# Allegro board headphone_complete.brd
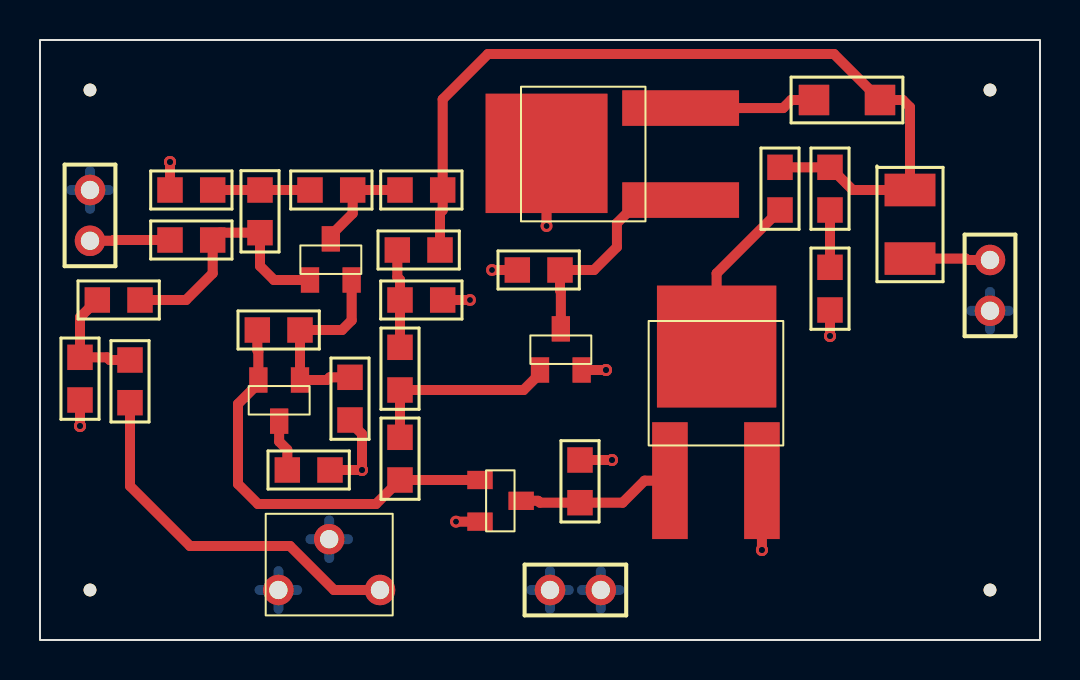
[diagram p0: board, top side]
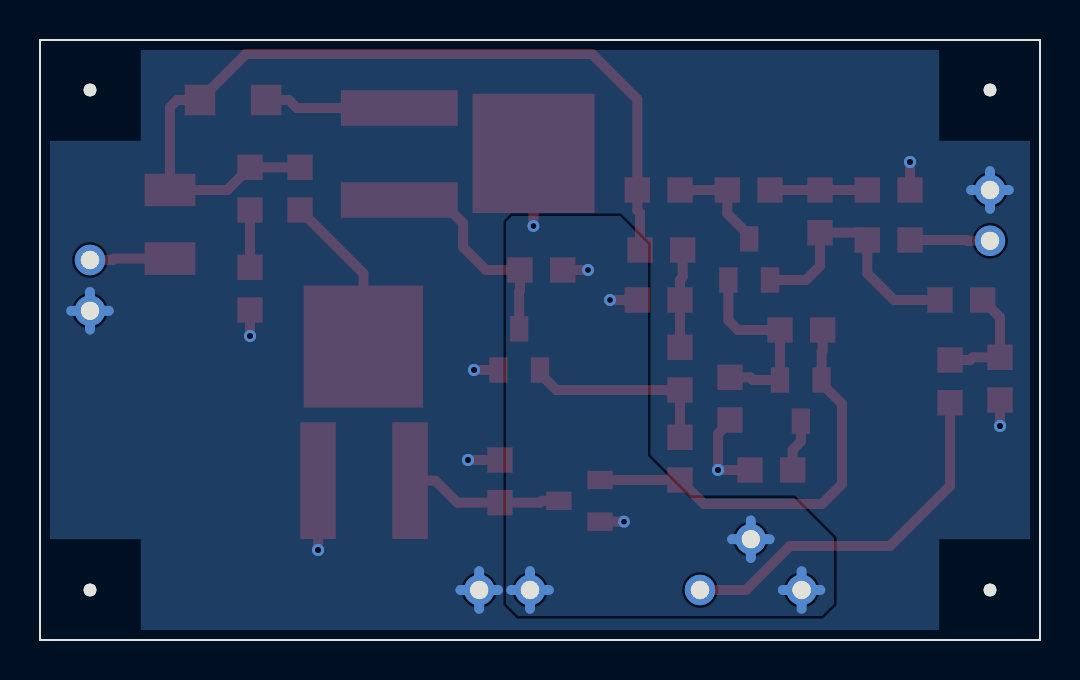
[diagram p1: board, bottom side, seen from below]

Outline 50 x 30 mm; copper layers: TOP, BOTTOM. Coordinates in mm from the lower left corner of the outline.
Outline path: rectangle 0,0 50,30

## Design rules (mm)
constraint set DEFAULT: min track width 0.5

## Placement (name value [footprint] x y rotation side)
C1  47u  [SMC0805]  20 19.5 180 top
C2  47u  [SMC0805]  2 12 90 top
C3  47u  [SMC0805]  13.5 22.5 0 top
C4  2200u  [SMC1210]  43.5 22.5 270 top
C5  0.47u  [SMC0805]  6.5 20 0 top
C6  10p  [SMC0805]  13 15.5 180 top
C7  0.1u  [SMC0805]  39.5 16.5 90 top
J1  HEADER 2  [JUMPER2]  2.5 22.5 270 top
J2  HEADER 2  [JUMPER2]  47.5 19 270 top
J3  HEADER 2  [JUMPER2]  25.5 2.5 0 top
NOREF  -  [unnamed]  47.5 27.5 0 top
NOREF#2  -  [unnamed]  47.5 2.5 0 top
NOREF#3  -  [unnamed]  2.5 27.5 0 top
NOREF#4  -  [unnamed]  2.5 2.5 0 top
Q1  TIP41  [TO252AA]  32 22 90 top
Q2  BC212AP/ZTX  [TO236AB]  25 13.5 270 top
Q3  BC212AP/ZTX  [TO236AB]  13.5 18 270 top
Q4  BC182BP/ZTX  [TO236AB]  22 8 180 top
Q5  TIP42  [TO252AA]  31.5 8 0 top
Q6  BC182BP/ZTX  [TO236AB]  13 13 90 top
R1  3k3  [SMR0805]  18 17 0 top
R2  1k8  [SMR0805]  26 18.5 180 top
R3  50k  [RESADJ]  17 2.5 270 top
R4  3k3  [SMR0805]  18 12.5 90 top
R5  22k  [SMR0805]  4.5 14 270 top
R6  2k2  [SMR0805]  18 22.5 0 top
R7  10  [SMR1206]  42 27 180 top
R8  560  [SMR0805]  18 8 90 top
R9  100k  [SMR0805]  5 17 180 top
R10  10  [SMR0805]  37 21.5 90 top
R11  10  [SMR0805]  39.5 21.5 90 top
R12  120k  [SMR0805]  11 22.5 270 top
R13  220  [SMR0805]  6.5 22.5 0 top
R14  2k2  [SMR0805]  15.5 11 90 top
R15  100  [SMR0805]  14.5 8.5 180 top
R16  1k8  [SMR0805]  27 9 270 top

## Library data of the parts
C1-C7 = C
J1-J3 = HEADER 2: User Part Number: ***
Q1 = TIP41
Q2 Q3 = BC212AP/ZTX_0
Q4 Q6 = BC182BP/ZTX_0
Q5 = TIP42
R1 R2 R4-R16 = R
R3 = POT: Tolerance: ***; User Part Number: ***

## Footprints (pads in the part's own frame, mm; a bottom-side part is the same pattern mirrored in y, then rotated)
JUMPER2
  round 1.524 hole 0.914: 1(0,0) 2(2.54,0)
RESADJ
  round 1.524 hole 0.914: 1(0,0) 2(-2.54,-2.54) 3(0,-5.08)
SMC0805
  rect 1.27x1.27 smd: 1(0,0) 2(2.134,0)
SMC1210
  rect 1.626x2.54 smd: 1(0,0) 2(3.429,0)
SMR0805
  rect 1.27x1.27 smd: 1(0,0) 2(2.134,0)
SMR1206
  rect 1.524x1.524 smd: 1(0,0) 2(3.302,0)
TO236AB
  rect 1.27x0.914 smd: 1(0,0) 2(0,2.083) 3(-2.057,1.041)
TO252AA
  rect 1.778x5.842 smd: 1(-0.004,-0.034) 3(4.596,-0.034)
  rect 5.969x6.096 smd: 2(2.332,6.673)
unnamed
  round 0.635 hole 3.175 unplated: (0,0)

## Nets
0: C2.1 C7.1 J1.1 J2.2 J3.2 Q2.2 Q5.3(E) R13.1 R14.1 R15.1 R16.1
IN: C5.1 J1.2
MID: C1.1 C4.1 R6.2 R7.1 R10.2 R11.2
OUT: C4.2 J2.1
VPP: J3.1 Q1.2 Q4.2 R1.2 R2.2 R3.2(T) R3.3
N1519156: C1.2 R1.1 R4.2
N1519228: Q1.1 Q2.3(E) R2.1
N1519232: R3.1 R5.2
N1519306: Q1.3(E) R7.2
N1519352: Q2.1 R4.1 R8.2
N1519356: C2.2 R5.1 R9.2
N1519362: C3.2 Q3.3(E) R6.1
N1519474: C3.1 R12.1 R13.2
N1519554: C6.2 Q4.1 Q6.2 R8.1
N1519560: C5.2 Q3.1 R9.1 R12.2
N1519748: C6.1 Q3.2 Q6.1 R14.2
N1519802: Q5.2 R10.1
N1519808: C7.2 R11.1
N1519834: Q4.3(E) Q5.1 R16.2
N1519922: Q6.3(E) R15.2

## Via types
v1: diameter 0.6, hole 0.3, TOP to BOTTOM, 18 vias

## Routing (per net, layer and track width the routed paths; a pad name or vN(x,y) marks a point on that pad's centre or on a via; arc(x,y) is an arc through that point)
0: length 25.9
  TOP w0.5: v1(39.5,15.2) C7.1 ; R14.1 15.5,10.9 16.1,10.3 v1(16.1,8.5) R15.1 ; v1(28.3,13.5) Q2.2 ; R13.1 v1(6.5,23.9) ; v1(2,10.7) C2.1 ; Q5.3 v1(36.1,4.5) ; R16.1 v1(28.6,9)
  BOTTOM w0.5: J1.1 2.5,23.44 ; J1.1 2.5,21.56 ; J1.1 1.56,22.5 ; J1.1 3.44,22.5 ; J2.2 48.44,16.46 ; J2.2 47.5,15.52 ; J2.2 46.56,16.46 ; J2.2 47.5,17.4 ; 28.04,1.56 J3.2 ; J3.2 28.04,3.44 ; J3.2 28.98,2.5 ; J3.2 27.1,2.5
IN: length 4
  TOP w0.5: J1.2 3.64,19.96 3.68,20 C5.1
MID: length 44.1
  TOP w0.5: C1.1 20,21.35 20.13,21.49 R6.2 20.13,27.03 22.4,29.3 39.7,29.3 R7.1 43.14,27 43.5,26.64 C4.1 40.63,22.5 R11.2 R10.2
OUT: length 4
  TOP w0.5: C4.2 46.29,19.07 46.36,19 J2.1
VPP: length 18.7
  TOP w0.5: R1.2 v1(21.5,17) ; Q1.2 v1(25.33,20.7) ; R2.2 v1(22.6,18.5) ; v1(20.8,5.92) Q4.2
  BOTTOM w0.5: 24.56,2.5 J3.1 ; J3.1 25.5,3.44 ; J3.1 26.44,2.5 ; J3.1 25.5,1.56 ; R3.2 14.46,5.98 ; R3.2 13.52,5.04 ; R3.2 14.46,4.1 ; R3.2 15.4,5.04 ; 11.92,1.56 R3.3 ; R3.3 10.98,2.5 ; R3.3 11.92,3.44 ; R3.3 12.86,2.5
N1519156: length 4.9
  TOP w0.5: R4.2 R1.1 18,18.01 17.87,18.15 C1.2
N1519228: length 11.1
  TOP w0.5: Q2.3 26.04,17.45 26,17.49 R2.1 27.7,18.5 28.85,19.65 28.85,20.84 30,22 Q1.1
N1519232: length 18.8
  TOP w0.5: R5.2 4.5,7.7 7.5,4.7 12.5,4.7 14.7,2.5 R3.1
N1519306: length 6.8
  TOP w0.5: R7.2 37.56,27 37.16,26.6 Q1.3
N1519352: length 9.9
  TOP w0.5: Q2.1 25,13.32 24.18,12.5 R4.1 R8.2
N1519356: length 5.8
  TOP w0.5: R5.1 3.49,14 3.35,14.13 C2.2 2,16.13 R9.2
N1519362: length 5.3
  TOP w0.5: Q3.3 14.54,20.24 15.63,21.33 C3.2 R6.1
N1519474: length 4.9
  TOP w0.5: R13.2 R12.1 C3.1
N1519554: length 21.2
  TOP w0.5: Q4.1 R8.1 16.8,6.8 10.9,6.8 9.9,7.8 9.9,11.8 10.92,12.82 Q6.2 10.92,14.44 10.87,14.49 C6.2
N1519560: length 12.8
  TOP w0.5: R9.1 7.3,17 8.63,18.33 C5.2 9,20.37 R12.2 11,18.7 11.7,18 Q3.1
N1519748: length 9.9
  TOP w0.5: R14.2 14.49,13.13 14.35,13 Q6.1 C6.1 15.1,15.5 15.58,15.98 Q3.2
N1519802: length 8.1
  TOP w0.5: Q5.2 33.83,18.33 R10.1
N1519808: length 2.9
  TOP w0.5: R11.1 C7.2
N1519834: length 7.9
  TOP w0.5: Q4.3 24.91,6.96 25,6.87 R16.2 29.13,6.87 30.23,7.97 Q5.1
N1519922: length 2.6
  TOP w0.5: R15.2 12.37,9.51 11.96,9.92 Q6.3

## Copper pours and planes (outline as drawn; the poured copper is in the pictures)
0 on BOTTOM: 49.5,0.5 0.5,0.5 0.5,29.5 49.5,29.5
VPP on BOTTOM: 26.7,1.8 26.7,20.9 26.4,21.2 21,21.2 19.6,19.8 19.6,9.2 17.5,7.1 12.3,7.1 10.3,5.1 10.3,1.8 10.9,1.2 26.1,1.2
